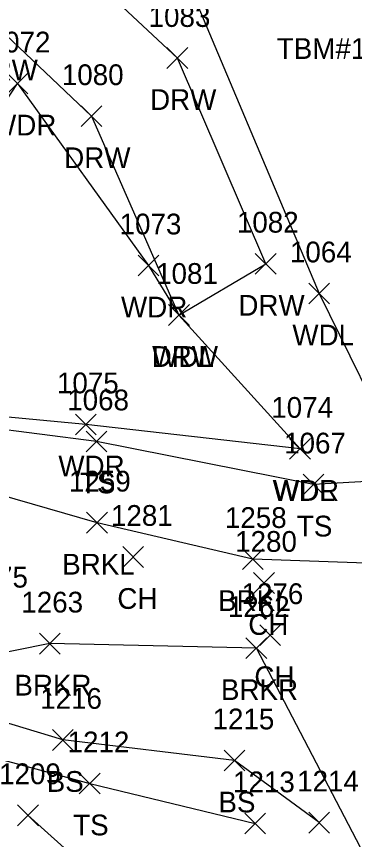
# Model space of a CAD drawing. Extents: x 1482574 to 1485769, y 580696 to 595649.
# Drawn here: x 1485196.7 to 1485229.3, y 581446.4 to 581525.7 of the extents above; entities that cross this region are included whole.
import ezdxf

# ---------------------------------------------------------------- set-up
doc = ezdxf.new("R2010")
doc.units = 0
for name, color, linetype in [('C_C', 7, 'Continuous'), ('L_A', 7, 'Continuous'), ('L_I', 7, 'Continuous'), ('L_TIC', 7, 'Continuous'), ('LAWA', 7, 'Continuous'), ('LAWE', 7, 'Continuous'), ('LELB', 7, 'Continuous'), ('R_A', 7, 'Continuous'), ('R_I', 7, 'Continuous'), ('R_TIC', 7, 'Continuous'), ('RDW', 7, 'Continuous')]:
    doc.layers.add(name, color=color, linetype=linetype)

msp = doc.modelspace()

# ---------------------------------------------------------------- linework, layer by layer
at = {"layer": 'L_TIC'}
for points in [[(1485195.839, 581518.191), (1485197.839, 581520.191)], [(1485197.839, 581518.191), (1485195.839, 581520.191)], [(1485208.451, 581500.659), (1485210.451, 581502.659)], [(1485210.451, 581500.659), (1485208.451, 581502.659)], [(1485224.901, 581497.965), (1485226.901, 581499.965)], [(1485226.901, 581497.965), (1485224.901, 581499.965)], [(1485211.397, 581495.895), (1485213.397, 581497.895)], [(1485213.397, 581495.895), (1485211.397, 581497.895)], [(1485202.414, 581485.35), (1485204.414, 581487.35)], [(1485204.414, 581485.35), (1485202.414, 581487.35)], [(1485203.451, 581483.71), (1485205.451, 581485.71)], [(1485205.451, 581483.71), (1485203.451, 581485.71)], [(1485223.057, 581482.991), (1485225.057, 581484.991)], [(1485225.057, 581482.991), (1485223.057, 581484.991)], [(1485223.057, 581482.991), (1485225.057, 581484.991)], [(1485225.057, 581482.991), (1485223.057, 581484.991)], [(1485224.343, 581479.556), (1485226.343, 581481.556)], [(1485226.343, 581479.556), (1485224.343, 581481.556)], [(1485203.503, 581475.885), (1485205.503, 581477.885)], [(1485205.503, 581475.885), (1485203.503, 581477.885)], [(1485206.974, 581472.581), (1485208.974, 581474.581)], [(1485208.974, 581472.581), (1485206.974, 581474.581)], [(1485218.513, 581472.378), (1485220.513, 581474.378)], [(1485220.513, 581472.378), (1485218.513, 581474.378)], [(1485219.586, 581470.078), (1485221.586, 581472.078)], [(1485221.586, 581470.078), (1485219.586, 581472.078)], [(1485220.17, 581465.045), (1485222.17, 581467.045)], [(1485222.17, 581465.045), (1485220.17, 581467.045)], [(1485198.953, 581464.231), (1485200.953, 581466.231)], [(1485200.953, 581464.231), (1485198.953, 581466.231)], [(1485218.848, 581463.802), (1485220.848, 581465.802)], [(1485220.848, 581463.802), (1485218.848, 581465.802)], [(1485200.209, 581454.953), (1485202.209, 581456.953)], [(1485202.209, 581454.953), (1485200.209, 581456.953)], [(1485216.755, 581452.972), (1485218.755, 581454.972)], [(1485218.755, 581452.972), (1485216.755, 581454.972)], [(1485202.798, 581450.76), (1485204.798, 581452.76)], [(1485204.798, 581450.76), (1485202.798, 581452.76)], [(1485196.853, 581447.693), (1485198.853, 581449.693)], [(1485198.853, 581447.693), (1485196.853, 581449.693)], [(1485218.73, 581446.915), (1485220.73, 581448.915)], [(1485220.73, 581446.915), (1485218.73, 581448.915)], [(1485224.904, 581446.987), (1485226.904, 581448.987)], [(1485226.904, 581446.987), (1485224.904, 581448.987)]]:
    msp.add_lwpolyline(points, dxfattribs=at)
at = {"layer": 'LAWA'}
for points in [[(1485204.864, 581806.832), (1485202.643, 581769.817), (1485202.407, 581732.616), (1485200.402, 581692.934), (1485199.008, 581656.996), (1485197.144, 581619.887), (1485194.202, 581587.659), (1485197.682, 581566.258), (1485198.112, 581555.169), (1485211.872, 581532.269), (1485225.901, 581498.965), (1485233.765, 581482.987)], [(1485183.211, 581489.047), (1485186.803, 581503.88), (1485196.839, 581519.191), (1485209.451, 581501.659)], [(1485209.451, 581501.659), (1485212.397, 581496.895)], [(1485224.057, 581483.991), (1485212.397, 581496.895)], [(1485224.057, 581483.991), (1485203.414, 581486.35), (1485187.062, 581487.889)]]:
    msp.add_lwpolyline(points, dxfattribs=at)
at = {"layer": 'LAWE'}
for points in [[(1485236.744, 581472.745), (1485219.513, 581473.378), (1485204.503, 581476.885), (1485188.673, 581481.419)], [(1485231.409, 581442.649), (1485219.848, 581464.802), (1485199.953, 581465.231), (1485189.753, 581463.204), (1485181.78, 581466.701)]]:
    msp.add_lwpolyline(points, dxfattribs=at)
at = {"layer": 'LELB'}
for points in [[(1485236.16, 581481.183), (1485225.343, 581480.556), (1485204.451, 581484.71), (1485193.444, 581486.117)], [(1485225.904, 581447.987), (1485217.755, 581453.972), (1485201.209, 581455.953), (1485192.807, 581458.486), (1485188.955, 581462.62)], [(1485184.116, 581460.907), (1485190.639, 581455.31), (1485203.798, 581451.76), (1485219.73, 581447.915)], [(1485219.198, 581424.152), (1485212.84, 581435.231), (1485197.853, 581448.693)]]:
    msp.add_lwpolyline(points, dxfattribs=at)
at = {"layer": 'R_TIC'}
for points in [[(1485211.243, 581520.652), (1485213.243, 581522.652)], [(1485213.243, 581520.652), (1485211.243, 581522.652)], [(1485202.972, 581515.045), (1485204.972, 581517.045)], [(1485204.972, 581515.045), (1485202.972, 581517.045)], [(1485219.747, 581500.832), (1485221.747, 581502.832)], [(1485221.747, 581500.832), (1485219.747, 581502.832)], [(1485211.397, 581495.895), (1485213.397, 581497.895)], [(1485213.397, 581495.895), (1485211.397, 581497.895)]]:
    msp.add_lwpolyline(points, dxfattribs=at)
at = {"layer": 'RDW'}
msp.add_lwpolyline([(1485178.562, 581519.939), (1485185.458, 581524.582), (1485195.048, 581524.503), (1485203.972, 581516.045), (1485212.397, 581496.895), (1485220.747, 581501.832), (1485212.243, 581521.652), (1485200.76, 581532.393), (1485186.685, 581539.27), (1485179.936, 581547.498)], dxfattribs=at)

# ---------------------------------------------------------------- texts
at = {"layer": 'C_C'}
msp.add_text('TBM#10 SIR S ASH', height=2, dxfattribs=at).set_placement((1485221.82, 581521.566))
at = {"layer": 'L_A'}
for s, p in [('WDR', (1485194.201, 581514.191)), ('WDR', (1485206.813, 581496.659)), ('WDL', (1485223.318, 581493.965)), ('WDL', (1485209.814, 581491.895)), ('WDR', (1485200.776, 581481.35)), ('TS', (1485202.86, 581479.71)), ('WDR', (1485221.419, 581478.991)), ('WDL', (1485221.474, 581478.991)), ('TS', (1485223.752, 581475.556)), ('BRKL', (1485201.149, 581471.885)), ('CH', (1485206.462, 581468.581)), ('BRKL', (1485216.159, 581468.378)), ('CH', (1485219.074, 581466.078)), ('CH', (1485219.658, 581461.045)), ('BRKR', (1485196.544, 581460.231)), ('BRKR', (1485216.439, 581459.802)), ('BS', (1485199.65, 581450.953)), ('BS', (1485216.196, 581448.972)), ('TS', (1485202.207, 581446.76))]:
    msp.add_text(s, height=2, dxfattribs=at).set_placement(p)
at = {"layer": 'L_I'}
for s, p in [('1072', (1485194.067, 581522.191)), ('1073', (1485206.679, 581504.659)), ('1064', (1485223.082, 581501.965)), ('1081', (1485210.192, 581499.895)), ('1075', (1485200.642, 581489.35)), ('1068', (1485201.632, 581487.71)), ('1074', (1485221.285, 581486.991)), ('1074', (1485221.285, 581486.991)), ('1067', (1485222.524, 581483.556)), ('1259', (1485201.802, 581479.885)), ('1281', (1485205.848, 581476.581)), ('1258', (1485216.82, 581476.378)), ('1280', (1485217.806, 581474.078)), ('1275', (1485191.899, 581470.633)), ('1276', (1485218.422, 581469.045)), ('1263', (1485197.213, 581468.231)), ('1262', (1485217.108, 581467.802)), ('1216', (1485199.028, 581458.953)), ('1215', (1485215.629, 581456.972)), ('1212', (1485201.672, 581454.76)), ('1209', (1485195.073, 581451.693)), ('1213', (1485217.604, 581450.915)), ('1214', (1485223.778, 581450.987))]:
    msp.add_text(s, height=2, dxfattribs=at).set_placement(p)
at = {"layer": 'R_A'}
for p in [(1485192.418, 581519.503), (1485209.613, 581516.652), (1485201.342, 581511.045), (1485218.117, 581496.832), (1485209.767, 581491.895)]:
    msp.add_text('DRW', height=2, dxfattribs=at).set_placement(p)
at = {"layer": 'R_I'}
for s, p in [('1083', (1485209.471, 581524.652)), ('1080', (1485201.114, 581519.045)), ('1082', (1485217.975, 581504.832)), ('1081', (1485210.192, 581499.895))]:
    msp.add_text(s, height=2, dxfattribs=at).set_placement(p)

doc.saveas('drawing.dxf')
